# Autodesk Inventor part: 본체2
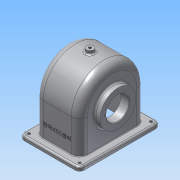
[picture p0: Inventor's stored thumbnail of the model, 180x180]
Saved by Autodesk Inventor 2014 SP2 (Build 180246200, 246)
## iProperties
Created: 2016-01
Part Number: 본체2
Material: 알루미늄 6061
Document SubType Name: Modeling
Designer: User
Mass: 809.57 g
Surface Area: 999.664 cm^2
Volume: 298.734 cm^3
Density: 2.71 g/cm^3
Appearance: 알루미늄 - 평지
Author: User
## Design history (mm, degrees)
sketch "스케치1"
  geometry: L1 (-57, 0)-(57, 0); L2 (57, 0)-(57, -64); L3 (57, -64)-(-57, -64); L4 (-57, -64)-(-57, 0); C1 r 57 at (0, 0); 2 further points
  constraints: 8 end point, 2 coincident, 2 parallel, 1 centre point, 1 horizontal, 1 midpoint, 1 perpendicular
  dimensions: "d0" = 114 diameter of C1; "d1" = 114 distance of L2.end L3.end; "d2" = 64 distance of L1.end L2.end
extrude "돌출1" new body sketch "스케치1" stored distance "d3" = 77; taper "d4" = 0 deg
feature "쉘1" dims "d7" = 6
sketch "스케치3"
  geometry: L1 (114, 0)-(114, -77) reference; L2 (0, 0)-(114, 0) reference; L3 (0, 0)-(0, -77) reference; L4 (114, -77)-(0, -77) reference; L5 (-13, 13.5)-(127, 13.5); L6 (127, 13.5)-(127, -90.5); L7 (127, -90.5)-(-13, -90.5); L8 (-13, -90.5)-(-13, 13.5); 3 further points
  constraints: 8 end point, 2 midpoint, 2 parallel, 1 horizontal, 1 horizontal alignment, 1 perpendicular, 1 vertical alignment
  dimensions: "d8" = 140 distance of L5.start L5.end; "d9" = 104 distance of L5.end L6.end
extrude "돌출2" join sketch "스케치3" distance "d10" = 7; taper "d11" = 0 deg
fillet "모깎기1" dims "d12" = 14
node "작업 평면1"
sketch "스케치6"
  geometry: C1 r 6 at (0, 0); 1 further point
  constraints: 1 centre point, 1 coincident
  dimensions: "d36" = 12 diameter of C1
extrude "돌출4" join sketch "스케치6" stored distance "d37" = 10; taper "d38" = 0 deg
hole "구멍2" diameter "d41" = 4.459; stored, may be unused: countersink angle "d45" = 90 deg, drill point angle "d47" = 118 deg; dims "d39" = 10, "d40" = 10, "d42" = 6, "d43" = 4, "d44" = 2, "d46" = 63
fillet "모깎기4" dims "d77" = 8
sketch "스케치9"
  geometry: A1 r 8 centre (119, 82.5) between (127, 82.5) and (119, 90.5) reference; A2 r 8 centre (-5, 82.5) between (-5, 90.5) and (-13, 82.5) reference; A3 r 8 centre (-5, -5.5) between (-13, -5.5) and (-5, -13.5) reference; A4 r 8 centre (119, -5.5) between (119, -13.5) and (127, -5.5) reference; 1 further point
hole "구멍5" sketch "스케치9" at (119, 82.5), (-5, 82.5), (119, -5.5), (-5, -5.5) diameter "d78" = 5; stored, may be unused: countersink angle "d82" = 90 deg, drill point angle "d84" = 118 deg; dims "d79" = 7, "d80" = 4, "d81" = 2, "d83" = 9
fillet "모깎기5" dims "d85" = 3
sketch "스케치10"
  geometry: L1 (49, 0)-(49, -57) reference; L2 (0, 0)-(49, 0) reference; L3 (0, -57)-(0, 0) reference; L4 (-1.387, -30.398)-(50.387, -30.398); L5 (50.387, -30.398)-(50.387, -37.602); L6 (50.387, -37.602)-(-1.387, -37.602); L7 (-1.387, -37.602)-(-1.387, -30.398); L8 (0, -34)-(49, -34); L9 (-19.5, -64)-(68.5, -64) reference; L10 (24.5, 0)-(24.5, -54); L11 (-14, 0)-(-14, -57) reference; L12 (68.5, -57)-(-19.5, -57) reference; 4 further points
  constraints: 4 end point, 4 midpoint, 2 point on line, 1 horizontal alignment, 1 perpendicular, 1 vertical alignment, 2 other
  dimensions: "d86" = 30 distance between parallel lines of L9 L8; "d87" = 38.5 distance between parallel lines of L11 L10
feature "엠보싱1" sketch "스케치10" dims "d8" = 140, "d9" = 104, "d88" = 0.5, "d89" = 0
sketch "스케치11"
  geometry: L1 (-51, -64)-(-51, 0) reference; L2 (51, -64)-(-51, -64) reference; L3 (51, 0)-(51, -64) reference; C1 r 20 at (0, -4) reference; A1 r 51 centre (0, 0) between (51, 0) and (-51, 0) reference
extrude "돌출5" cut sketch "스케치11" distance "d90" = 1; taper "d91" = 0 deg
sketch "스케치12"
  geometry: L1 (-51, -64)-(-51, 0) reference; L2 (51, -64)-(-51, -64) reference; L3 (51, 0)-(51, -64) reference; C1 r 38.908 at (0, -4) reference; A1 r 51 centre (0, 0) between (51, 0) and (-51, 0) reference
extrude "돌출6" cut sketch "스케치12" distance "d92" = 1; taper "d93" = 0 deg
sketch "스케치13"
  geometry: L1 (-4, 43.197)-(-4, -48.942); L2 (-64, -33.5)-(-64, 33.5) reference; L3 (16, 35.5)-(30.899, 35.5); L4 (24, 35.5)-(24, 19.5); L5 (24, 19.5)-(16, 19.5); L6 (16, 19.5)-(16, 35.5); L7 (0, 38.5)-(43, 38.5) reference; L8 (24, 19.5)-(39.943, 38.5); L9 (30.899, 35.5)-(33.416, 38.5); L10 (-4, 33.5)-(16, 33.5); L11 (-4, 38.5)-(33.416, 38.5); L12 (-4, 38.5)-(-4, 33.5); 1 further point
  constraints: 20 end point, 6 point on line, 3 parallel, 2 perpendicular, 1 collinear, 1 horizontal, 1 vertical
  dimensions: "d95" = 60 distance between parallel lines of L1 L2; "d96" = 20 distance between parallel lines of L1 L6; "d99" = 50 deg angle of L8 L5; "d100" = 5 distance between parallel lines of L8 L9; "d102" = 5 distance between parallel lines of L10 L11; "d103" = 56 diameter of L4 L1; "d104" = 19 distance between parallel lines of L11 L5; "d105" = 3 distance between parallel lines of L11 L3
revolve "회전3" stored, may be unused: angle "d106" = 90 deg
revolve "회전4" stored, may be unused: angle "d107" = 90 deg
sketch "스케치14"
  geometry: C1 r 20 at (0, -4) reference; C2 r 31 at (0, -4)
  constraints: 1 centre point, 1 coincident
  dimensions: "d108" = 62 diameter of C2
extrude "돌출7" join sketch "스케치14" distance "d109" = 10; taper "d110" = 0 deg
hole "구멍6" diameter "d113" = 40; stored, may be unused: countersink angle "d117" = 90 deg, drill point angle "d119" = 118 deg; dims "d111" = 10, "d112" = 10, "d114" = 6, "d115" = 4, "d116" = 2, "d118" = 8
chamfer "모따기3" distance "d120" = 1; stored, may be unused: second distance "d121" = 2, angle "d122" = 45 deg
fillet "모깎기6" dims "d123" = 3
sketch "스케치15"
  geometry: C1 r 31 at (0, 0) reference; 2 further points
  constraints: 1 vertical alignment
  dimensions: "d124" = 24 distance of C1.centre point (0, 24)
hole "구멍7" sketch "스케치15" at (0, 24) diameter "d125" = 2.459; stored, may be unused: countersink angle "d129" = 90 deg, drill point angle "d131" = 118 deg; dims "d126" = 6, "d127" = 4, "d128" = 2, "d130" = 8
sketch "스케치16"
  geometry: C1 r 21 at (0, 0) reference; 2 further points
  constraints: 1 vertical alignment
  dimensions: "d135" = 28 distance of C1.centre point (0, 28)
hole "구멍8" sketch "스케치16" at (0, 28) diameter "d136" = 2.459; stored, may be unused: countersink angle "d140" = 90 deg, drill point angle "d142" = 118 deg; dims "d137" = 7, "d138" = 4, "d139" = 2, "d141" = 9
fillet "모깎기7" dims "d146" = 9
fillet "모깎기8" dims "d147" = 3
fillet "모깎기9" dims "d148" = 1
node "솔리드1"
pattern_circular "원형 패턴3" dims angle "d133" = 360 deg
pattern_circular "원형 패턴4" dims angle "d144" = 360 deg
other parameters: "d35" = 63
